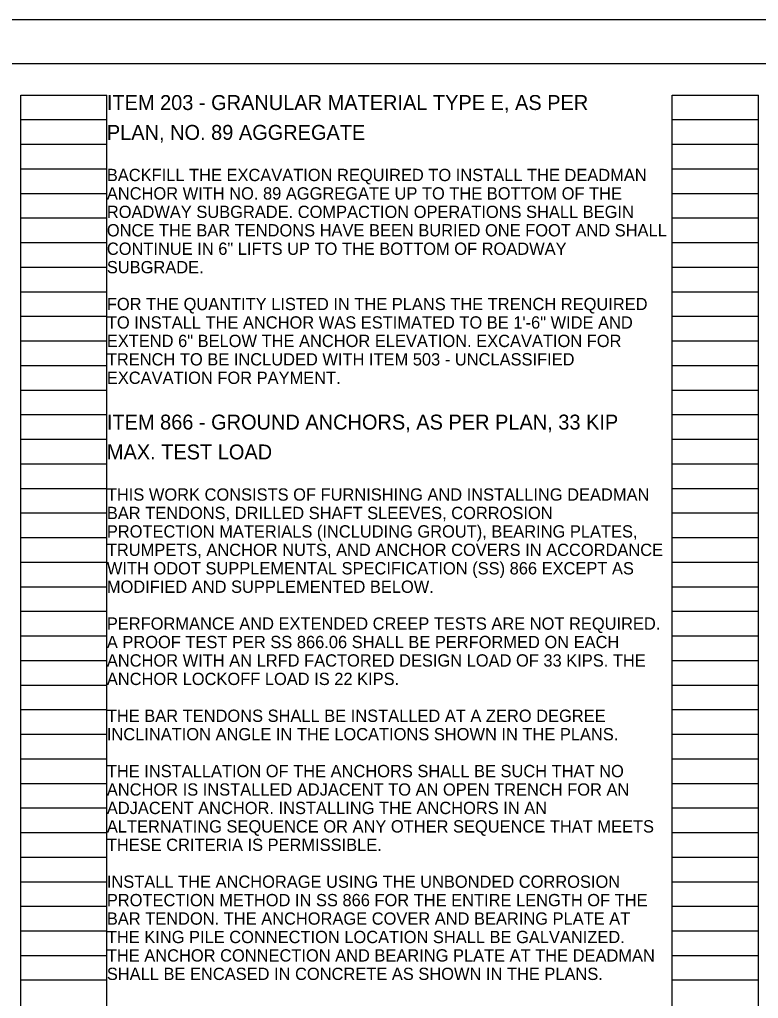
# Model space of a CAD drawing. Extents: x -0.2 to 33.8, y -0.1 to 21.9.
# Drawn here: x 16.52 to 24.94, y 10.72 to 21.87 of the extents above; entities that cross this region are included whole.
import ezdxf

# ---------------------------------------------------------------- set-up
doc = ezdxf.new("R2010")
doc.units = 0
for name, color, linetype in [('SH_Border', 7, 'Continuous'), ('SH_Cut_Line', 7, 'Continuous'), ('SH_Data', 7, 'Continuous')]:
    doc.layers.add(name, color=color, linetype=linetype)

msp = doc.modelspace()

# ---------------------------------------------------------------- linework, layer by layer
at = {"layer": 'SH_Border'}
msp.add_lwpolyline([(1.775, 21.368), (33.275, 21.368), (33.275, 0.368), (1.775, 0.368)], close=True, dxfattribs=at)
at = {"layer": 'SH_Cut_Line'}
msp.add_lwpolyline([(-0.225, 21.868), (33.775, 21.868), (33.775, -0.132), (-0.225, -0.132)], close=True, dxfattribs=at)
at = {"layer": 'SH_Data'}
for p, q in [((16.535, 0.848), (16.535, 21.008)), ((16.535, 21.008), (17.515, 21.008)), ((17.515, 0.848), (17.515, 21.008)), ((23.955, 0.848), (23.955, 21.008)), ((23.955, 21.008), (24.935, 21.008)), ((24.935, 0.848), (24.935, 21.008)), ((16.535, 20.728), (17.515, 20.728)), ((23.955, 20.728), (24.935, 20.728)), ((16.535, 20.448), (17.515, 20.448)), ((23.955, 20.448), (24.935, 20.448)), ((16.535, 20.168), (17.515, 20.168)), ((23.955, 20.168), (24.935, 20.168)), ((16.535, 19.888), (17.515, 19.888)), ((23.955, 19.888), (24.935, 19.888)), ((16.535, 19.608), (17.515, 19.608)), ((23.955, 19.608), (24.935, 19.608)), ((16.535, 19.328), (17.515, 19.328)), ((23.955, 19.328), (24.935, 19.328)), ((16.535, 19.048), (17.515, 19.048)), ((23.955, 19.048), (24.935, 19.048)), ((16.535, 18.768), (17.515, 18.768)), ((23.955, 18.768), (24.935, 18.768)), ((16.535, 18.488), (17.515, 18.488)), ((23.955, 18.488), (24.935, 18.488)), ((16.535, 18.208), (17.515, 18.208)), ((23.955, 18.208), (24.935, 18.208)), ((16.535, 17.928), (17.515, 17.928)), ((23.955, 17.928), (24.935, 17.928)), ((16.535, 17.648), (17.515, 17.648)), ((23.955, 17.648), (24.935, 17.648)), ((16.535, 17.368), (17.515, 17.368)), ((23.955, 17.368), (24.935, 17.368)), ((16.535, 17.088), (17.515, 17.088)), ((23.955, 17.088), (24.935, 17.088)), ((16.535, 16.808), (17.515, 16.808)), ((23.955, 16.808), (24.935, 16.808)), ((16.535, 16.528), (17.515, 16.528)), ((23.955, 16.528), (24.935, 16.528)), ((16.535, 16.248), (17.515, 16.248)), ((23.955, 16.248), (24.935, 16.248)), ((16.535, 15.968), (17.515, 15.968)), ((23.955, 15.968), (24.935, 15.968)), ((16.535, 15.688), (17.515, 15.688)), ((23.955, 15.688), (24.935, 15.688)), ((16.535, 15.408), (17.515, 15.408)), ((23.955, 15.408), (24.935, 15.408)), ((16.535, 15.128), (17.515, 15.128)), ((23.955, 15.128), (24.935, 15.128)), ((16.535, 14.848), (17.515, 14.848)), ((23.955, 14.848), (24.935, 14.848)), ((16.535, 14.568), (17.515, 14.568)), ((23.955, 14.568), (24.935, 14.568)), ((16.535, 14.288), (17.515, 14.288)), ((23.955, 14.288), (24.935, 14.288)), ((16.535, 14.008), (17.515, 14.008)), ((23.955, 14.008), (24.935, 14.008)), ((16.535, 13.728), (17.515, 13.728)), ((23.955, 13.728), (24.935, 13.728)), ((16.535, 13.448), (17.515, 13.448)), ((23.955, 13.448), (24.935, 13.448)), ((16.535, 13.168), (17.515, 13.168)), ((23.955, 13.168), (24.935, 13.168)), ((16.535, 12.888), (17.515, 12.888)), ((23.955, 12.888), (24.935, 12.888)), ((16.535, 12.608), (17.515, 12.608)), ((23.955, 12.608), (24.935, 12.608)), ((16.535, 12.328), (17.515, 12.328)), ((23.955, 12.328), (24.935, 12.328)), ((16.535, 12.048), (17.515, 12.048)), ((23.955, 12.048), (24.935, 12.048)), ((16.535, 11.768), (17.515, 11.768)), ((23.955, 11.768), (24.935, 11.768)), ((16.535, 11.488), (17.515, 11.488)), ((23.955, 11.488), (24.935, 11.488)), ((16.535, 11.208), (17.515, 11.208)), ((23.955, 11.208), (24.935, 11.208)), ((16.535, 10.928), (17.515, 10.928)), ((23.955, 10.928), (24.935, 10.928))]:
    msp.add_line(p, q, dxfattribs=at)

# ---------------------------------------------------------------- texts
for s, height, p in [('ITEM 203 - GRANULAR MATERIAL TYPE E, AS PER ', 0.17, (17.515, 20.838)), ('PLAN, NO. 89 AGGREGATE', 0.17, (17.515, 20.498)), ('BACKFILL THE EXCAVATION REQUIRED TO INSTALL THE DEADMAN ', 0.14, (17.515, 20.028)), ('ANCHOR WITH NO. 89 AGGREGATE UP TO THE BOTTOM OF THE ', 0.14, (17.515, 19.818)), ('ROADWAY SUBGRADE. COMPACTION OPERATIONS SHALL BEGIN ', 0.14, (17.515, 19.608)), ('ONCE THE BAR TENDONS HAVE BEEN BURIED ONE FOOT AND SHALL ', 0.14, (17.515, 19.398)), ('CONTINUE IN 6" LIFTS UP TO THE BOTTOM OF ROADWAY ', 0.14, (17.515, 19.188)), ('SUBGRADE.', 0.14, (17.515, 18.978)), ('FOR THE QUANTITY LISTED IN THE PLANS THE TRENCH REQUIRED ', 0.14, (17.515, 18.558)), ('TO INSTALL THE ANCHOR WAS ESTIMATED TO BE 1\'-6" WIDE AND ', 0.14, (17.515, 18.348)), ('EXTEND 6" BELOW THE ANCHOR ELEVATION. EXCAVATION FOR ', 0.14, (17.515, 18.138)), ('TRENCH TO BE INCLUDED WITH ITEM 503 - UNCLASSIFIED ', 0.14, (17.515, 17.928)), ('EXCAVATION FOR PAYMENT.', 0.14, (17.515, 17.718)), ('ITEM 866 - GROUND ANCHORS, AS PER PLAN, 33 KIP ', 0.17, (17.515, 17.198)), ('MAX. TEST LOAD', 0.17, (17.515, 16.858)), ('THIS WORK CONSISTS OF FURNISHING AND INSTALLING DEADMAN ', 0.14, (17.515, 16.388)), ('BAR TENDONS, DRILLED SHAFT SLEEVES, CORROSION ', 0.14, (17.515, 16.178)), ('PROTECTION MATERIALS (INCLUDING GROUT), BEARING PLATES, ', 0.14, (17.515, 15.968)), ('TRUMPETS, ANCHOR NUTS, AND ANCHOR COVERS IN ACCORDANCE ', 0.14, (17.515, 15.758)), ('WITH ODOT SUPPLEMENTAL SPECIFICATION (SS) 866 EXCEPT AS ', 0.14, (17.515, 15.548)), ('MODIFIED AND SUPPLEMENTED BELOW.', 0.14, (17.515, 15.338)), ('PERFORMANCE AND EXTENDED CREEP TESTS ARE NOT REQUIRED. ', 0.14, (17.515, 14.918)), ('A PROOF TEST PER SS 866.06 SHALL BE PERFORMED ON EACH ', 0.14, (17.515, 14.708)), ('ANCHOR WITH AN LRFD FACTORED DESIGN LOAD OF 33 KIPS. THE ', 0.14, (17.515, 14.498)), ('ANCHOR LOCKOFF LOAD IS 22 KIPS.', 0.14, (17.515, 14.288)), ('THE BAR TENDONS SHALL BE INSTALLED AT A ZERO DEGREE ', 0.14, (17.515, 13.868)), ('INCLINATION ANGLE IN THE LOCATIONS SHOWN IN THE PLANS.', 0.14, (17.515, 13.658)), ('THE INSTALLATION OF THE ANCHORS SHALL BE SUCH THAT NO ', 0.14, (17.515, 13.238)), ('ANCHOR IS INSTALLED ADJACENT TO AN OPEN TRENCH FOR AN ', 0.14, (17.515, 13.028)), ('ADJACENT ANCHOR. INSTALLING THE ANCHORS IN AN ', 0.14, (17.515, 12.818)), ('ALTERNATING SEQUENCE OR ANY OTHER SEQUENCE THAT MEETS ', 0.14, (17.515, 12.608)), ('THESE CRITERIA IS PERMISSIBLE.', 0.14, (17.515, 12.398)), ('INSTALL THE ANCHORAGE USING THE UNBONDED CORROSION ', 0.14, (17.515, 11.978)), ('PROTECTION METHOD IN SS 866 FOR THE ENTIRE LENGTH OF THE ', 0.14, (17.515, 11.768)), ('BAR TENDON. THE ANCHORAGE COVER AND BEARING PLATE AT ', 0.14, (17.515, 11.558)), ('THE KING PILE CONNECTION LOCATION SHALL BE GALVANIZED. ', 0.14, (17.515, 11.348)), ('THE ANCHOR CONNECTION AND BEARING PLATE AT THE DEADMAN ', 0.14, (17.515, 11.138)), ('SHALL BE ENCASED IN CONCRETE AS SHOWN IN THE PLANS. ', 0.14, (17.515, 10.928))]:
    msp.add_text(s, height=height, dxfattribs=at).set_placement(p)

doc.saveas('drawing.dxf')
